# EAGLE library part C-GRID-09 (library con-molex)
CONNECTOR wire to board 2.54 mm (0.100") pitch header
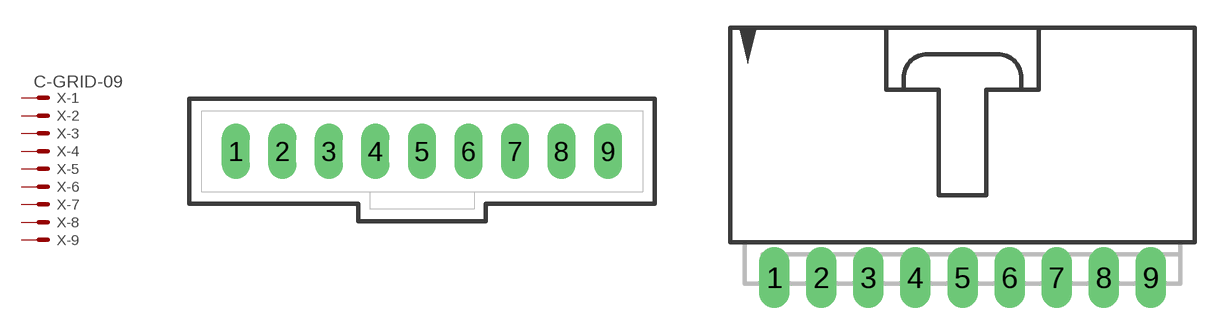
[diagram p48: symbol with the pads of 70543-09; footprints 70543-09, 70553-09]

Designator prefix X; gates -1=MV -2=M -3=M -4=M -5=M -6=M -7=M -8=M -9=M

## C-GRID-09-70543 (OC_FARNELL: unknown; OC_NEWARK: unknown)  [70543-09]
1  -1:S  pas
2  -2:S  pas
3  -3:S  pas
4  -4:S  pas
5  -5:S  pas
6  -6:S  pas
7  -7:S  pas
8  -8:S  pas
9  -9:S  pas

## C-GRID-09-70553 (OC_FARNELL: unknown; OC_NEWARK: unknown)  [70553-09]
Pads as for 70543-09

## C-GRID-09-74099 (OC_FARNELL: unknown; OC_NEWARK: unknown)  [74099-09]
Pads as for 70543-09

## C-GRID-09-15-91 (OC_FARNELL: unknown; OC_NEWARK: unknown)  [15-91-09]
Pads as for 70543-09

## Footprint 70543-09 (pad centres in mm)
C-Grid SL Connector vertical, 9 pin
drill 1.016 long: 1 -10.16,0; 2 -7.62,0; 3 -5.08,0; 4 -2.54,0; 5 0,0; 6 2.54,0; 7 5.08,0; 8 7.62,0; 9 10.16,0

## Footprint 70553-09 (pad centres in mm)
C-Grid SL Connector right angle, 9 pin
drill 1.092 long: 1 -10.16,-7.62; 2 -7.62,-7.62; 3 -5.08,-7.62; 4 -2.54,-7.62; 5 0,-7.62; 6 2.54,-7.62; 7 5.08,-7.62; 8 7.62,-7.62; 9 10.16,-7.62

## Footprint 74099-09 (pad centres in mm)
C-Grid SL Connector vertical SMD, 9 pin
smd 1.27 x 3.175: 1 -10.16,-2.223; 2 -7.62,2.223; 3 -5.08,-2.223; 4 -2.54,2.223; 5 0,-2.223; 6 2.54,2.223; 7 5.08,-2.223; 8 7.62,2.223; 9 10.16,-2.223

## Footprint 15-91-09 (pad centres in mm)
C-Grid SL Connector right angle SMD, 9 pin
smd 1.651 x 5.334: 1 -10.16,-10.795; 2 -7.62,-10.795; 3 -5.08,-10.795; 4 -2.54,-10.795; 5 0,-10.795; 6 2.54,-10.795; 7 5.08,-10.795; 8 7.62,-10.795; 9 10.16,-10.795
hole 3.404 at -11.557,0.838
hole 3.404 at 11.557,0.838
